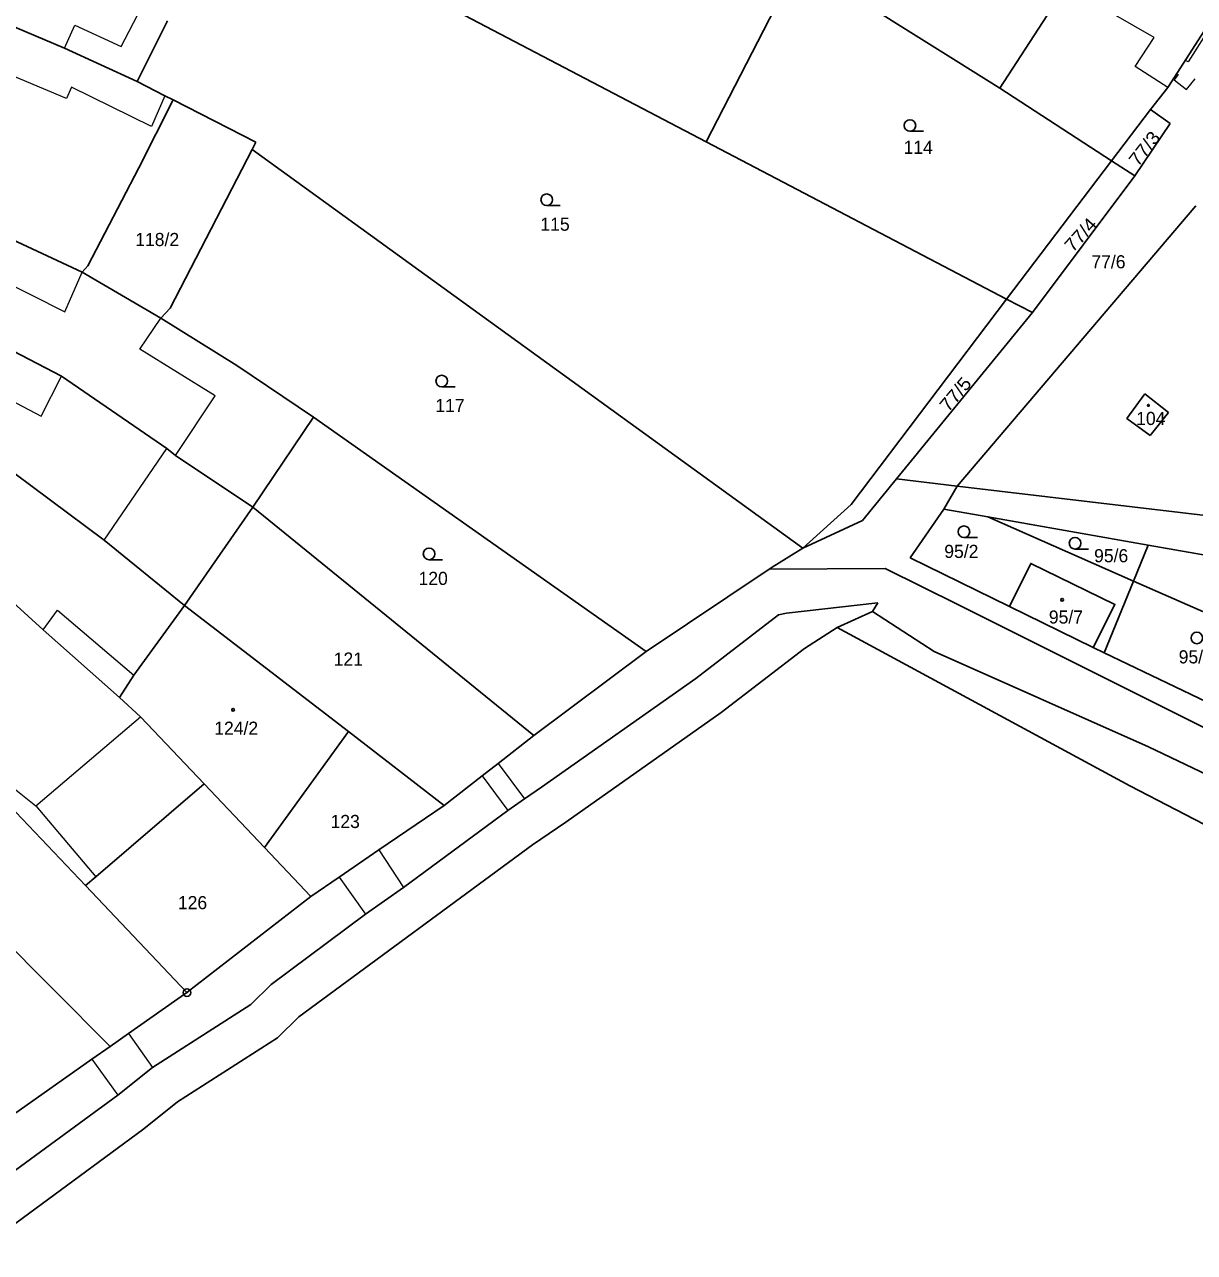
# Model space of a CAD drawing. Extents: x -606517 to -602431, y -1183120 to -1179397.
# Drawn here: x -605477.8 to -605326.3, y -1181159.4 to -1181000.2 of the extents above; entities that cross this region are included whole.
import ezdxf
from ezdxf.enums import TextEntityAlignment as Align

# ---------------------------------------------------------------- set-up
doc = ezdxf.new("R2010")
doc.units = 0
doc.header["$LTSCALE"] = 0.68
for name, color, linetype, lineweight in [('1', 7, 'Continuous', 25), ('13', 7, 'Continuous', 13), ('3', 7, 'Continuous', 25), ('4', 7, 'Continuous', 13), ('5', 7, 'Continuous', 25), ('8', 7, 'Continuous', 25)]:
    doc.layers.add(name, color=color, linetype=linetype, lineweight=lineweight)
doc.layers.add('2', color=7, linetype='Continuous')

msp = doc.modelspace()

# ---------------------------------------------------------------- linework, layer by layer
at = {"layer": '1'}
for p, q in [((-605389.53, -1181015.4), (-605377.52, -1180992.12)), ((-605351.46, -1181008.45), (-605377.52, -1180992.12)), ((-605486.25, -1180997.56), (-605472.64, -1181003.28)), ((-605425.76, -1180996.41), (-605389.53, -1181015.4)), ((-605329.72, -1181008.39), (-605322.19, -1180996.66)), ((-605345.4, -1180999.09), (-605351.46, -1181008.45)), ((-605463.26, -1181007.59), (-605459.3, -1180999.75)), ((-605472.64, -1181003.28), (-605463.26, -1181007.59)), ((-605463.26, -1181007.59), (-605459.64, -1181009.45)), ((-605351.46, -1181008.45), (-605337, -1181017.87)), ((-605331.95, -1181011.22), (-605329.72, -1181008.39)), ((-605458.57, -1181009.99), (-605463.03, -1181018.77)), ((-605459.64, -1181009.45), (-605458.57, -1181009.99)), ((-605458.57, -1181009.99), (-605447.88, -1181015.47)), ((-605337, -1181017.87), (-605331.95, -1181011.22)), ((-605331.95, -1181011.22), (-605329.39, -1181013.03)), ((-605329.39, -1181013.03), (-605333.97, -1181019.84)), ((-605389.53, -1181015.4), (-605350.61, -1181035.79)), ((-605452.32, -1181024.11), (-605448.36, -1181016.41)), ((-605447.88, -1181015.47), (-605448.36, -1181016.41)), ((-605448.36, -1181016.41), (-605377.01, -1181068.08)), ((-605350.61, -1181035.79), (-605337, -1181017.87)), ((-605333.97, -1181019.84), (-605337, -1181017.87)), ((-605463.03, -1181018.77), (-605469.64, -1181031.48)), ((-605333.97, -1181019.84), (-605347.26, -1181037.55)), ((-605470.39, -1181032.32), (-605494.64, -1181021.01)), ((-605458.96, -1181036.98), (-605452.32, -1181024.11)), ((-605357.02, -1181060.03), (-605326.09, -1181023.72)), ((-605498.42, -1181032.59), (-605473.06, -1181045.78)), ((-605469.64, -1181031.48), (-605470.39, -1181032.32)), ((-605460.18, -1181038.28), (-605470.39, -1181032.32)), ((-605370.72, -1181062.42), (-605350.61, -1181035.79)), ((-605347.26, -1181037.55), (-605350.61, -1181035.79)), ((-605460.18, -1181038.28), (-605458.96, -1181036.98)), ((-605347.26, -1181037.55), (-605364.85, -1181059.09)), ((-605450.32, -1181044.39), (-605460.18, -1181038.28)), ((-605440.38, -1181051.11), (-605450.32, -1181044.39)), ((-605473.06, -1181045.78), (-605459.4, -1181055.18)), ((-605335, -1181051.3), (-605332.7, -1181048.1)), ((-605332.7, -1181048.1), (-605329.6, -1181050.5)), ((-605440.38, -1181051.11), (-605448.25, -1181062.78)), ((-605397.28, -1181081.5), (-605440.38, -1181051.11)), ((-605332, -1181053.5), (-605335, -1181051.3)), ((-605329.6, -1181050.5), (-605332, -1181053.5)), ((-605467.51, -1181067.03), (-605483.98, -1181054.78)), ((-605459.4, -1181055.18), (-605458.28, -1181056.07)), ((-605458.28, -1181056.07), (-605448.25, -1181062.78)), ((-605364.85, -1181059.09), (-605369.26, -1181064.5)), ((-605357.02, -1181060.03), (-605364.85, -1181059.09)), ((-605358.75, -1181063.03), (-605357.02, -1181060.03)), ((-605322.18, -1181064.16), (-605357.02, -1181060.03)), ((-605448.25, -1181062.78), (-605457.11, -1181075.51)), ((-605448.25, -1181062.78), (-605411.86, -1181092.39)), ((-605377.01, -1181068.08), (-605370.72, -1181062.42)), ((-605363.07, -1181069.36), (-605358.75, -1181063.03)), ((-605353.03, -1181064.04), (-605358.75, -1181063.03)), ((-605369.26, -1181064.5), (-605377.01, -1181068.08)), ((-605353.03, -1181064.04), (-605334.15, -1181072.37)), ((-605332.24, -1181067.72), (-605353.03, -1181064.04)), ((-605457.11, -1181075.51), (-605467.51, -1181067.03)), ((-605334.15, -1181072.37), (-605332.24, -1181067.72)), ((-605304.35, -1181072.51), (-605332.24, -1181067.72)), ((-605377.01, -1181068.08), (-605380.97, -1181070.54)), ((-605350.24, -1181075.65), (-605363.07, -1181069.36)), ((-605397.28, -1181081.5), (-605381.37, -1181070.81)), ((-605380.97, -1181070.54), (-605381.37, -1181070.81)), ((-605381.37, -1181070.81), (-605366.34, -1181070.74)), ((-605366.34, -1181070.74), (-605356.82, -1181075.45)), ((-605337.96, -1181081.67), (-605334.15, -1181072.37)), ((-605334.15, -1181072.37), (-605310.87, -1181082.62)), ((-605481.28, -1181073.36), (-605475.43, -1181078.67)), ((-605457.11, -1181075.51), (-605463.69, -1181084.57)), ((-605435.88, -1181091.87), (-605457.11, -1181075.51)), ((-605379.12, -1181076.52), (-605367.29, -1181075.18)), ((-605367.29, -1181075.18), (-605367.97, -1181076.28)), ((-605356.82, -1181075.45), (-605319.69, -1181094.02)), ((-605339.38, -1181080.97), (-605350.24, -1181075.65)), ((-605390.86, -1181084.98), (-605380.13, -1181076.73)), ((-605380.13, -1181076.73), (-605379.12, -1181076.52)), ((-605367.97, -1181076.28), (-605372.55, -1181078.37)), ((-605360, -1181081.5), (-605367.97, -1181076.28)), ((-605475.43, -1181078.67), (-605465.53, -1181087.44)), ((-605372.55, -1181078.37), (-605376.78, -1181081.09)), ((-605372.55, -1181078.37), (-605334.62, -1181098.91)), ((-605411.86, -1181092.39), (-605397.28, -1181081.5)), ((-605376.78, -1181081.09), (-605387.6, -1181089.4)), ((-605332.19, -1181093.85), (-605360, -1181081.5)), ((-605337.96, -1181081.67), (-605339.38, -1181080.97)), ((-605316.79, -1181091.8), (-605337.96, -1181081.67)), ((-605463.69, -1181084.57), (-605465.53, -1181087.44)), ((-605410.84, -1181099.08), (-605390.86, -1181084.98)), ((-605465.53, -1181087.44), (-605462.8, -1181089.95)), ((-605469.95, -1181111.83), (-605490.44, -1181090.22)), ((-605462.8, -1181089.95), (-605454.58, -1181098.63)), ((-605387.6, -1181089.4), (-605407.7, -1181103.6)), ((-605446.74, -1181106.91), (-605435.88, -1181091.87)), ((-605423.48, -1181101.43), (-605435.88, -1181091.87)), ((-605416.47, -1181095.98), (-605411.86, -1181092.39)), ((-605504.74, -1181094.54), (-605466.73, -1181132.68)), ((-605300.23, -1181109.15), (-605332.19, -1181093.85)), ((-605418.56, -1181097.6), (-605416.47, -1181095.98)), ((-605423.48, -1181101.43), (-605418.56, -1181097.6)), ((-605454.58, -1181098.63), (-605468.61, -1181110.68)), ((-605454.58, -1181098.63), (-605446.74, -1181106.91)), ((-605413.04, -1181100.58), (-605410.84, -1181099.08)), ((-605334.62, -1181098.91), (-605310.86, -1181111.19)), ((-605415.23, -1181102.08), (-605413.04, -1181100.58)), ((-605431.92, -1181107.2), (-605423.48, -1181101.43)), ((-605428.74, -1181112.08), (-605415.23, -1181102.08)), ((-605407.7, -1181103.6), (-605412.04, -1181106.56)), ((-605446.74, -1181106.91), (-605440.74, -1181113.23)), ((-605412.04, -1181106.56), (-605442.32, -1181128.83)), ((-605437.09, -1181110.73), (-605431.92, -1181107.2)), ((-605468.61, -1181110.68), (-605469.95, -1181111.83)), ((-605440.74, -1181113.23), (-605437.09, -1181110.73)), ((-605456.8, -1181125.7), (-605469.95, -1181111.83)), ((-605433.65, -1181115.55), (-605428.74, -1181112.08)), ((-605456.8, -1181125.7), (-605440.74, -1181113.23)), ((-605445.9, -1181124.64), (-605433.65, -1181115.55)), ((-605448.53, -1181127.23), (-605445.9, -1181124.64)), ((-605464.38, -1181131.02), (-605456.8, -1181125.7)), ((-605461.24, -1181135.4), (-605448.53, -1181127.23)), ((-605442.32, -1181128.83), (-605445.07, -1181131.54)), ((-605466.73, -1181132.68), (-605464.38, -1181131.02)), ((-605445.07, -1181131.54), (-605458.02, -1181139.87)), ((-605469.1, -1181134.34), (-605466.73, -1181132.68)), ((-605479.29, -1181141.5), (-605469.1, -1181134.34)), ((-605465.74, -1181139.01), (-605461.24, -1181135.4)), ((-605482.61, -1181151.33), (-605465.74, -1181139.01)), ((-605458.02, -1181139.87), (-605462.39, -1181143.37)), ((-605462.39, -1181143.37), (-605484.12, -1181159.38))]:
    msp.add_line(p, q, dxfattribs=at)
msp.add_lwpolyline([(-605350.24, -1181075.65), (-605347.47, -1181070.07), (-605336.57, -1181075.38), (-605339.38, -1181080.97)], dxfattribs=at)
at = {"layer": '13'}
msp.add_lwpolyline([(-605321.88, -1180996.84), (-605327.07, -1181005.06), (-605327.35, -1181004.93), (-605327.46, -1181004.86), (-605328.57, -1181006.59), (-605328.37, -1181006.7), (-605328.89, -1181007.37), (-605327.27, -1181008.63), (-605326.18, -1181007.24)], dxfattribs=at)
at = {"layer": '3'}
for p, q in [((-605363.113, -1181014.05), (-605361.363, -1181014.05)), ((-605410.183, -1181023.67), (-605408.433, -1181023.67)), ((-605423.793, -1181047.17), (-605422.043, -1181047.17)), ((-605356.123, -1181066.7), (-605354.373, -1181066.7)), ((-605341.733, -1181068.2), (-605339.983, -1181068.2)), ((-605425.423, -1181069.58), (-605423.673, -1181069.58))]:
    msp.add_line(p, q, dxfattribs=at)
for centre in [(-605363.1129, -1181013.2998), (-605410.1829, -1181022.9198), (-605423.7929, -1181046.4198), (-605356.1229, -1181065.9498), (-605341.7329, -1181067.4498), (-605425.4229, -1181068.8298), (-605325.9529, -1181079.7298)]:
    msp.add_circle(centre, 0.75, dxfattribs=at)
at = {"layer": '4'}
for p, q in [((-605331.48, -1181001.89), (-605339.07, -1180997.52)), ((-605465.34, -1181003.07), (-605462.68, -1180998.01)), ((-605472.64, -1181003.28), (-605471.31, -1181000.3)), ((-605471.31, -1181000.3), (-605465.34, -1181003.07)), ((-605333.94, -1181005.65), (-605331.48, -1181001.89)), ((-605472.4, -1181009.79), (-605482.33, -1181005.62)), ((-605329.72, -1181008.39), (-605333.94, -1181005.65)), ((-605471.74, -1181008.33), (-605472.4, -1181009.79)), ((-605461.4, -1181013.44), (-605471.74, -1181008.33)), ((-605459.64, -1181009.45), (-605461.4, -1181013.44)), ((-605482.51, -1181032.49), (-605472.63, -1181037.45)), ((-605472.63, -1181037.45), (-605470.39, -1181032.32)), ((-605462.89, -1181042.3), (-605460.18, -1181038.28)), ((-605493.16, -1181041.89), (-605475.69, -1181050.96)), ((-605453.14, -1181048.34), (-605462.89, -1181042.3)), ((-605475.69, -1181050.96), (-605473.06, -1181045.78)), ((-605458.28, -1181056.07), (-605453.14, -1181048.34)), ((-605467.51, -1181067.03), (-605459.4, -1181055.18)), ((-605475.43, -1181078.67), (-605473.57, -1181076.12)), ((-605473.57, -1181076.12), (-605463.69, -1181084.57)), ((-605490.44, -1181090.22), (-605476.38, -1181101.49)), ((-605476.38, -1181101.49), (-605462.8, -1181089.95)), ((-605416.47, -1181095.98), (-605413.04, -1181100.58)), ((-605418.56, -1181097.6), (-605415.23, -1181102.08)), ((-605476.38, -1181101.49), (-605468.61, -1181110.68)), ((-605431.92, -1181107.2), (-605428.74, -1181112.08)), ((-605437.09, -1181110.73), (-605433.65, -1181115.55)), ((-605464.38, -1181131.02), (-605461.24, -1181135.4)), ((-605469.1, -1181134.34), (-605465.74, -1181139.01))]:
    msp.add_line(p, q, dxfattribs=at)
at = {"layer": '5'}
for centre, radius in [((-605332.2246, -1181049.5794), 0.1172), ((-605343.4068, -1181074.7792), 0.175), ((-605450.8268, -1181089.0292), 0.175)]:
    msp.add_circle(centre, radius, dxfattribs=at)
at = {"layer": '8'}
for radius in [0.5, 0.0303]:
    msp.add_circle((-605456.8, -1181125.6999), radius, dxfattribs=at)

# ---------------------------------------------------------------- texts
at = {"layer": '2'}
for s, p in [('114', (-605363.95, -1181016.975)), ('115', (-605411, -1181026.945)), ('117', (-605424.61, -1181050.445)), ('104', (-605333.81, -1181052.125)), ('95/2', (-605358.67, -1181069.355)), ('95/6', (-605339.26, -1181069.915)), ('120', (-605426.79, -1181072.855)), ('121', (-605437.78, -1181083.315)), ('95/4', (-605328.3, -1181083.025)), ('124/2', (-605453.26, -1181092.275)), ('123', (-605438.19, -1181104.365)), ('126', (-605457.97, -1181114.885))]:
    msp.add_text(s, height=1.7, dxfattribs=at).set_placement(p)
at = {"layer": '2', "width": 1.1}
for s, rotation, p in [('77/3', 52, (-605332.0668, -1181016.8043)), ('77/4', 48, (-605340.3734, -1181028.0243)), ('77/5', 50, (-605356.5705, -1181048.6739))]:
    msp.add_text(s, height=1.7, rotation=rotation, dxfattribs=at).set_placement(p, align=Align.CENTER)
at = {"layer": '2'}
for s, p in [('118/2', (-605460.65, -1181028.925)), ('77/6', (-605337.399, -1181031.815)), ('95/7', (-605342.909, -1181077.865))]:
    msp.add_text(s, height=1.7, dxfattribs=at).set_placement(p, align=Align.CENTER)

doc.saveas('drawing.dxf')
